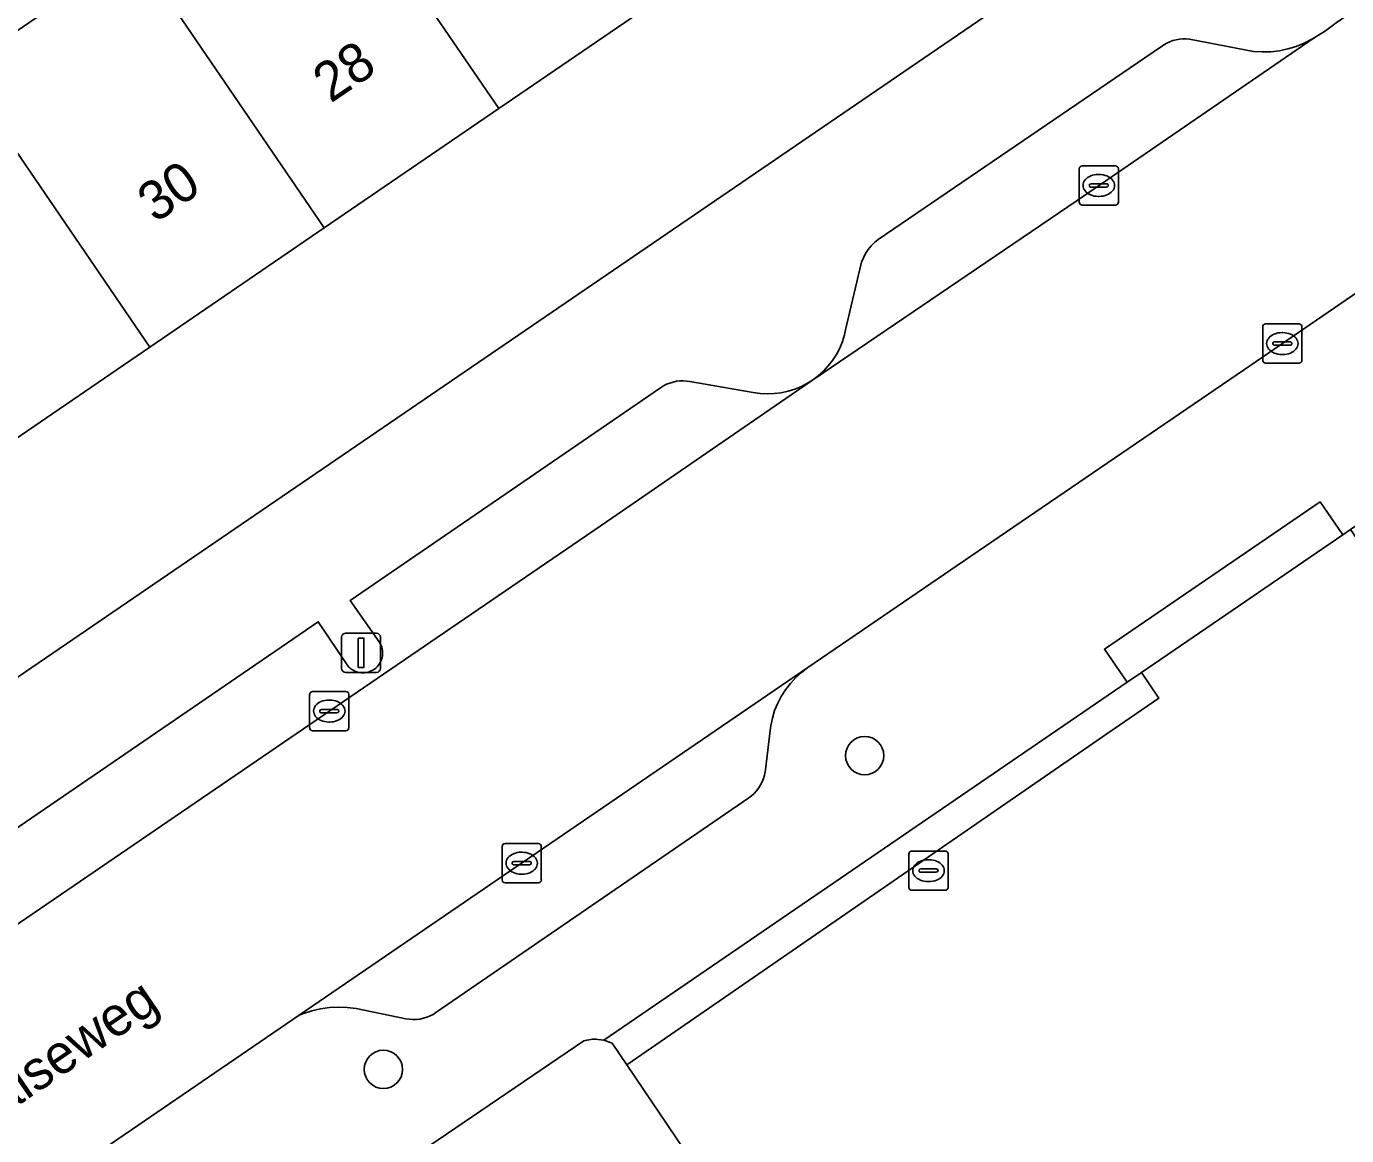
# Model space of a CAD drawing. Extents: x 157445 to 158888, y 383061 to 384688.
# Drawn here: x 158247.86 to 158281.55, y 383719.45 to 383747.74 of the extents above; entities that cross this region are included whole.
import ezdxf

# ---------------------------------------------------------------- set-up
doc = ezdxf.new("R2010")
doc.units = 0
for name, color, linetype in [('IMGEO_Boom', 7, 'Continuous'), ('IMGEO_Erf', 7, 'Continuous'), ('IMGEO_Groenvoorziening', 7, 'Continuous'), ('IMGEO_Kolk', 7, 'Continuous'), ('IMGEO_Lichtmast', 7, 'Continuous'), ('IMGEO_Openbare_ruimte_label', 7, 'Continuous'), ('IMGEO_Pand', 7, 'Continuous'), ('IMGEO_Pand_nummerreeks', 7, 'Continuous'), ('IMGEO_Parkeervlak_open', 7, 'Continuous'), ('IMGEO_Rijbaan_lokaal_open', 7, 'Continuous'), ('IMGEO_Voetpad_gesloten', 7, 'Continuous'), ('IMGEO_Voetpad_open', 7, 'Continuous')]:
    doc.layers.add(name, color=color, linetype=linetype)

msp = doc.modelspace()

# ---------------------------------------------------------------- linework, layer by layer
at = {"layer": 'IMGEO_Boom'}
for centre in [(158269.25, 383729.141), (158256.968, 383721.134)]:
    msp.add_circle(centre, 0.489, dxfattribs=at)
at = {"layer": 'IMGEO_Erf'}
msp.add_lwpolyline([(158275.244, 383750), (158276.273, 383750.703), (158273.392, 383754.863), (158268.814, 383751.734), (158266.277, 383750), (158264.363, 383748.692), (158259.911, 383745.649), (158255.46, 383742.607), (158251.008, 383739.564), (158246.557, 383736.522), (158242.105, 383733.479), (158237.653, 383730.437), (158233.201, 383727.394), (158228.626, 383724.267), (158231.45, 383720.093)], close=True, dxfattribs=at)
at = {"layer": 'IMGEO_Groenvoorziening'}
msp.add_lwpolyline([(158276.313, 383731.261), (158275.946, 383731.01), (158262.596, 383721.878), (158262.806, 383721.806), (158263.183, 383721.249), (158275.456, 383729.709), (158276.755, 383730.605)], close=True, dxfattribs=at)
for points in [[(158262.079, 383721.862), (158245.028, 383710.284), (158233.32, 383702.286)], [(158274.181, 383704.979), (158272.403, 383707.609), (158263.183, 383721.249), (158262.806, 383721.806), (158262.596, 383721.878), (158262.44, 383721.901)]]:
    msp.add_lwpolyline(points, dxfattribs=at)
msp.add_arc((158262.365, 383720.907), 0.997, 85.6714, 106.6604, dxfattribs=at)
at = {"layer": 'IMGEO_Kolk'}
for p, q in [((158274.725, 383743.26), (158274.725, 383744.112)), ((158274.8, 383744.186), (158275.652, 383744.186)), ((158275.726, 383744.112), (158275.726, 383743.26)), ((158274.984, 383743.68), (158274.984, 383743.692)), ((158275.027, 383743.729), (158275.425, 383743.729)), ((158275.213, 383743.966), (158275.238, 383743.966)), ((158275.468, 383743.692), (158275.468, 383743.68)), ((158275.422, 383743.643), (158275.024, 383743.643)), ((158275.236, 383743.406), (158275.211, 383743.406)), ((158275.652, 383743.186), (158274.8, 383743.186)), ((158279.409, 383739.226), (158279.409, 383740.078)), ((158279.484, 383740.152), (158280.336, 383740.152)), ((158280.41, 383740.078), (158280.41, 383739.226)), ((158279.668, 383739.646), (158279.668, 383739.658)), ((158279.711, 383739.695), (158280.109, 383739.695)), ((158279.897, 383739.932), (158279.922, 383739.932)), ((158280.152, 383739.658), (158280.152, 383739.646)), ((158280.106, 383739.609), (158279.708, 383739.609)), ((158279.92, 383739.372), (158279.895, 383739.372)), ((158280.336, 383739.152), (158279.484, 383739.152)), ((158255.086, 383729.85), (158255.086, 383730.702)), ((158255.161, 383730.776), (158256.013, 383730.776)), ((158255.574, 383730.556), (158255.599, 383730.556)), ((158256.087, 383730.702), (158256.087, 383729.85)), ((158255.345, 383730.27), (158255.345, 383730.282)), ((158255.783, 383730.233), (158255.385, 383730.233)), ((158255.388, 383730.319), (158255.786, 383730.319)), ((158255.829, 383730.282), (158255.829, 383730.27)), ((158255.597, 383729.996), (158255.572, 383729.996)), ((158256.013, 383729.776), (158255.161, 383729.776)), ((158259.997, 383725.969), (158259.997, 383726.821)), ((158260.072, 383726.895), (158260.924, 383726.895)), ((158260.998, 383726.821), (158260.998, 383725.969)), ((158260.485, 383726.675), (158260.51, 383726.675)), ((158270.379, 383725.779), (158270.379, 383726.631)), ((158270.454, 383726.705), (158271.306, 383726.705)), ((158270.867, 383726.485), (158270.892, 383726.485)), ((158271.38, 383726.631), (158271.38, 383725.779)), ((158260.256, 383726.389), (158260.256, 383726.401)), ((158260.694, 383726.352), (158260.296, 383726.352)), ((158260.299, 383726.438), (158260.697, 383726.438)), ((158260.74, 383726.401), (158260.74, 383726.389)), ((158270.638, 383726.199), (158270.638, 383726.211)), ((158271.076, 383726.162), (158270.678, 383726.162)), ((158270.681, 383726.248), (158271.079, 383726.248)), ((158271.122, 383726.211), (158271.122, 383726.199)), ((158260.924, 383725.895), (158260.072, 383725.895)), ((158260.508, 383726.115), (158260.483, 383726.115)), ((158270.89, 383725.925), (158270.865, 383725.925)), ((158271.306, 383725.705), (158270.454, 383725.705))]:
    msp.add_line(p, q, dxfattribs=at)
for points in [[(158274.725, 383743.26), (158274.725, 383744.112)], [(158274.8, 383744.186), (158275.652, 383744.186)], [(158275.726, 383744.112), (158275.726, 383743.26)], [(158275.652, 383743.186), (158274.8, 383743.186)], [(158279.409, 383739.226), (158279.409, 383740.078)], [(158279.484, 383740.152), (158280.336, 383740.152)], [(158280.41, 383740.078), (158280.41, 383739.226)], [(158280.336, 383739.152), (158279.484, 383739.152)], [(158255.086, 383729.85), (158255.086, 383730.702)], [(158255.161, 383730.776), (158256.013, 383730.776)], [(158256.087, 383730.702), (158256.087, 383729.85)], [(158256.013, 383729.776), (158255.161, 383729.776)], [(158259.997, 383725.969), (158259.997, 383726.821)], [(158260.072, 383726.895), (158260.924, 383726.895)], [(158260.998, 383726.821), (158260.998, 383725.969)], [(158270.379, 383725.779), (158270.379, 383726.631)], [(158270.454, 383726.705), (158271.306, 383726.705)], [(158271.38, 383726.631), (158271.38, 383725.779)], [(158260.924, 383725.895), (158260.072, 383725.895)], [(158271.306, 383725.705), (158270.454, 383725.705)]]:
    msp.add_lwpolyline(points, dxfattribs=at)
for centre, radius, start, end in [((158274.802, 383744.11), 0.0765, 91.552, 178.448), ((158274.802, 383744.11), 0.0765, 91.552, 178.448), ((158275.65, 383744.11), 0.0765, 1.552, 88.448), ((158275.65, 383744.11), 0.0765, 1.552, 88.448), ((158275.024, 383743.689), 0.0403, 85.8775, 175.7526), ((158275.021, 383743.679), 0.0366, 178.938, 274.7102), ((158275.425, 383743.686), 0.043, 264.8664, 352.4533), ((158275.429, 383743.691), 0.0386, 1.7309, 96.639), ((158274.802, 383743.262), 0.0765, 181.552, 268.448), ((158274.802, 383743.262), 0.0765, 181.552, 268.448), ((158275.65, 383743.262), 0.0765, 271.552, 358.448), ((158275.65, 383743.262), 0.0765, 271.552, 358.448), ((158279.486, 383740.076), 0.0765, 91.552, 178.448), ((158279.486, 383740.076), 0.0765, 91.552, 178.448), ((158280.334, 383740.076), 0.0765, 1.552, 88.448), ((158280.334, 383740.076), 0.0765, 1.552, 88.448), ((158279.708, 383739.655), 0.0403, 85.8775, 175.7526), ((158279.705, 383739.645), 0.0366, 178.938, 274.7102), ((158280.109, 383739.652), 0.043, 264.8664, 352.4533), ((158280.113, 383739.657), 0.0386, 1.7309, 96.639), ((158279.486, 383739.228), 0.0765, 181.552, 268.448), ((158279.486, 383739.228), 0.0765, 181.552, 268.448), ((158280.334, 383739.228), 0.0765, 271.552, 358.448), ((158280.334, 383739.228), 0.0765, 271.552, 358.448), ((158255.163, 383730.7), 0.0765, 91.552, 178.448), ((158255.163, 383730.7), 0.0765, 91.552, 178.448), ((158256.011, 383730.7), 0.0765, 1.552, 88.448), ((158256.011, 383730.7), 0.0765, 1.552, 88.448), ((158255.385, 383730.279), 0.0403, 85.8775, 175.7526), ((158255.382, 383730.269), 0.0366, 178.938, 274.7102), ((158255.786, 383730.276), 0.043, 264.8664, 352.4533), ((158255.79, 383730.281), 0.0386, 1.7309, 96.639), ((158255.163, 383729.852), 0.0765, 181.552, 268.448), ((158255.163, 383729.852), 0.0765, 181.552, 268.448), ((158256.011, 383729.852), 0.0765, 271.552, 358.448), ((158256.011, 383729.852), 0.0765, 271.552, 358.448), ((158260.074, 383726.819), 0.0765, 91.552, 178.448), ((158260.074, 383726.819), 0.0765, 91.552, 178.448), ((158260.922, 383726.819), 0.0765, 1.552, 88.448), ((158260.922, 383726.819), 0.0765, 1.552, 88.448), ((158270.456, 383726.629), 0.0765, 91.552, 178.448), ((158270.456, 383726.629), 0.0765, 91.552, 178.448), ((158271.304, 383726.629), 0.0765, 1.552, 88.448), ((158271.304, 383726.629), 0.0765, 1.552, 88.448), ((158260.296, 383726.398), 0.0403, 85.8775, 175.7526), ((158260.293, 383726.388), 0.0366, 178.938, 274.7102), ((158260.697, 383726.395), 0.043, 264.8664, 352.4533), ((158260.701, 383726.4), 0.0386, 1.7309, 96.639), ((158270.678, 383726.208), 0.0403, 85.8775, 175.7526), ((158270.675, 383726.198), 0.0366, 178.938, 274.7102), ((158271.079, 383726.205), 0.043, 264.8664, 352.4533), ((158271.083, 383726.21), 0.0386, 1.7309, 96.639), ((158260.074, 383725.971), 0.0765, 181.552, 268.448), ((158260.074, 383725.971), 0.0765, 181.552, 268.448), ((158260.922, 383725.971), 0.0765, 271.552, 358.448), ((158260.922, 383725.971), 0.0765, 271.552, 358.448), ((158270.456, 383725.781), 0.0765, 181.552, 268.448), ((158270.456, 383725.781), 0.0765, 181.552, 268.448), ((158271.304, 383725.781), 0.0765, 271.552, 358.448), ((158271.304, 383725.781), 0.0765, 271.552, 358.448)]:
    msp.add_arc(centre, radius, start, end, dxfattribs=at)
for centre, major_axis, ratio, start_param, end_param in [((158275.212, 383743.686), (-0.387, 0.002), 0.722429, 4.712389, 7.853982), ((158275.237, 383743.686), (-0.39, 0.002), 0.717154, 1.570796, 4.712389), ((158279.896, 383739.652), (-0.387, 0.002), 0.722429, 4.712389, 7.853982), ((158279.921, 383739.652), (-0.39, 0.002), 0.717154, 1.570796, 4.712389), ((158255.573, 383730.276), (-0.387, 0.002), 0.722429, 4.712389, 7.853982), ((158255.598, 383730.276), (-0.39, 0.002), 0.717154, 1.570796, 4.712389), ((158260.484, 383726.395), (-0.387, 0.002), 0.722429, 4.712389, 7.853982), ((158260.509, 383726.395), (-0.39, 0.002), 0.717154, 1.570796, 4.712389), ((158270.866, 383726.205), (-0.387, 0.002), 0.722429, 4.712389, 7.853982), ((158270.891, 383726.205), (-0.39, 0.002), 0.717154, 1.570796, 4.712389)]:
    msp.add_ellipse(centre, major_axis=major_axis, ratio=ratio, start_param=start_param, end_param=end_param, dxfattribs=at)
at = {"layer": 'IMGEO_Lichtmast'}
for p, q in [((158256.002, 383732.263), (158256.792, 383732.263)), ((158256.792, 383732.263), (158256.002, 383732.263)), ((158255.902, 383731.363), (158255.902, 383732.163)), ((158255.902, 383732.163), (158255.902, 383731.363)), ((158256.892, 383732.163), (158256.892, 383731.363)), ((158256.892, 383731.363), (158256.892, 383732.163)), ((158256.792, 383731.263), (158256.002, 383731.263)), ((158256.002, 383731.263), (158256.792, 383731.263))]:
    msp.add_line(p, q, dxfattribs=at)
msp.add_lwpolyline([(158256.322, 383732.138), (158256.472, 383732.138), (158256.472, 383731.388), (158256.322, 383731.388), (158256.322, 383732.138)], dxfattribs=at)
for centre, start, end in [((158256.002, 383732.163), 90, 180), ((158256.002, 383732.163), 90, 180), ((158256.792, 383732.163), 0, 90), ((158256.792, 383732.163), 360, 90), ((158256.002, 383731.363), 180, 270), ((158256.002, 383731.363), 180, 270), ((158256.792, 383731.363), 270, 0), ((158256.792, 383731.363), 270, 0)]:
    msp.add_arc(centre, 0.1, start, end, dxfattribs=at)
at = {"layer": 'IMGEO_Pand'}
for points in [[(158259.524, 383755.771), (158255.072, 383752.729), (158256.938, 383750), (158259.911, 383745.649), (158264.363, 383748.692), (158263.469, 383750)], [(158250.62, 383749.688), (158255.46, 383742.607), (158259.911, 383745.649), (158256.938, 383750), (158255.072, 383752.729), (158251.077, 383750)], [(158250.62, 383749.688), (158246.168, 383746.646), (158251.008, 383739.564), (158255.46, 383742.607)], [(158241.716, 383743.605), (158246.557, 383736.522), (158251.008, 383739.564), (158246.168, 383746.646)]]:
    msp.add_lwpolyline(points, close=True, dxfattribs=at)
at = {"layer": 'IMGEO_Parkeervlak_open'}
for points in [[(158301.094, 383734.058), (158304.262, 383729.417), (158318.912, 383739.463), (158311.696, 383750), (158309.812, 383752.752), (158295.206, 383742.73), (158297.657, 383739.109), (158294.925, 383737.259), (158292.253, 383741.181), (158283.359, 383735.114), (158282.098, 383734.254), (158281.649, 383734.911), (158281.45, 383734.775), (158276.313, 383731.261), (158276.755, 383730.605), (158275.456, 383729.709), (158263.183, 383721.249), (158272.403, 383707.609), (158274.095, 383708.785), (158301.564, 383727.539), (158298.373, 383732.165)], [(158267.916, 383738.718), (158274.673, 383743.3), (158280.721, 383747.449), (158280.664, 383747.416), (158280.467, 383747.315), (158280.262, 383747.232), (158280.051, 383747.168), (158279.834, 383747.123), (158279.615, 383747.098), (158279.394, 383747.092), (158279.173, 383747.106), (158277.543, 383747.415), (158277.458, 383747.424), (158277.372, 383747.425), (158277.286, 383747.419), (158277.201, 383747.405), (158277.118, 383747.383), (158277.038, 383747.354), (158276.96, 383747.318), (158276.885, 383747.275), (158276.815, 383747.226), (158276.797, 383747.212), (158269.591, 383742.311), (158269.5, 383742.231), (158269.416, 383742.143), (158269.341, 383742.048), (158269.274, 383741.947), (158269.217, 383741.84), (158269.169, 383741.729), (158269.157, 383741.694), (158268.765, 383740.002), (158268.736, 383739.876), (158268.682, 383739.704), (158268.613, 383739.536), (158268.529, 383739.376), (158268.431, 383739.223), (158268.32, 383739.08), (158268.196, 383738.947), (158268.061, 383738.826)], [(158267.801, 383731.384), (158254.816, 383722.516), (158254.93, 383722.562), (158255.145, 383722.632), (158255.366, 383722.683), (158255.591, 383722.713), (158255.818, 383722.724), (158256.044, 383722.714), (158256.269, 383722.684), (158257.543, 383722.426), (158257.632, 383722.412), (158257.722, 383722.407), (158257.812, 383722.409), (158257.901, 383722.42), (158257.989, 383722.438), (158258.075, 383722.464), (158258.158, 383722.498), (158258.238, 383722.539), (158258.307, 383722.582), (158266.293, 383728.062), (158266.365, 383728.116), (158266.431, 383728.177), (158266.492, 383728.243), (158266.547, 383728.315), (158266.595, 383728.391), (158266.636, 383728.471), (158266.67, 383728.554), (158266.696, 383728.64), (158266.715, 383728.729), (158266.721, 383728.774), (158266.835, 383729.78), (158266.852, 383729.899), (158266.894, 383730.096), (158266.953, 383730.288), (158267.03, 383730.474), (158267.123, 383730.652), (158267.231, 383730.822), (158267.354, 383730.981), (158267.491, 383731.129), (158267.64, 383731.263)]]:
    msp.add_lwpolyline(points, close=True, dxfattribs=at)
msp.add_lwpolyline([(158234.944, 383716.183), (158262.66, 383735.101), (158267.916, 383738.718), (158267.793, 383738.641), (158267.634, 383738.558), (158267.467, 383738.489), (158267.295, 383738.436), (158267.119, 383738.398), (158266.94, 383738.376), (158266.76, 383738.37), (158266.58, 383738.38), (158266.402, 383738.406), (158264.789, 383738.683), (158264.703, 383738.696), (158264.617, 383738.701), (158264.53, 383738.699), (158264.444, 383738.689), (158264.359, 383738.671), (158264.276, 383738.645), (158264.196, 383738.613), (158264.119, 383738.573), (158264.041, 383738.523), (158256.121, 383733.101), (158256.857, 383732.043), (158256.868, 383732.026), (158256.891, 383731.987), (158256.91, 383731.947), (158256.925, 383731.904), (158256.936, 383731.861), (158256.944, 383731.816), (158256.947, 383731.771), (158256.947, 383731.726), (158256.942, 383731.682), (158256.934, 383731.637), (158256.921, 383731.594), (158256.905, 383731.552), (158256.885, 383731.512), (158256.862, 383731.473), (158256.835, 383731.437), (158256.805, 383731.403), (158256.772, 383731.373), (158256.737, 383731.345), (158256.699, 383731.32), (158256.659, 383731.299), (158256.618, 383731.282), (158256.575, 383731.268), (158256.531, 383731.259), (158256.486, 383731.253), (158256.441, 383731.251), (158256.396, 383731.253), (158256.351, 383731.26), (158256.308, 383731.27), (158256.265, 383731.284), (158256.224, 383731.302), (158256.184, 383731.324), (158256.147, 383731.349), (158256.111, 383731.377), (158256.079, 383731.408), (158255.304, 383732.556), (158236.556, 383719.728)], dxfattribs=at)
at = {"layer": 'IMGEO_Rijbaan_lokaal_open'}
for points in [[(158330.351, 383781.361), (158307.283, 383765.552), (158290.185, 383753.958), (158290.116, 383753.905), (158281.286, 383747.838), (158281.012, 383747.631), (158280.721, 383747.449), (158274.673, 383743.3), (158267.916, 383738.718), (158262.66, 383735.101), (158234.944, 383716.183)], [(158248.547, 383718.234), (158254.816, 383722.516), (158267.801, 383731.384), (158272.686, 383734.719), (158278.94, 383738.991), (158282.459, 383741.394), (158290.097, 383746.61), (158295.037, 383750), (158330.85, 383774.628)]]:
    msp.add_lwpolyline(points, dxfattribs=at)
at = {"layer": 'IMGEO_Voetpad_gesloten'}
msp.add_lwpolyline([(158281.45, 383734.775), (158280.874, 383735.617), (158275.37, 383731.852), (158275.946, 383731.01), (158276.313, 383731.261)], close=True, dxfattribs=at)
at = {"layer": 'IMGEO_Voetpad_open'}
for points in [[(158275.244, 383750), (158231.45, 383720.093)], [(158236.556, 383719.728), (158255.304, 383732.556), (158256.079, 383731.408), (158256.111, 383731.377), (158256.147, 383731.349), (158256.184, 383731.324), (158256.224, 383731.302), (158256.265, 383731.284), (158256.308, 383731.27), (158256.351, 383731.26), (158256.396, 383731.253), (158256.441, 383731.251), (158256.486, 383731.253), (158256.531, 383731.259), (158256.575, 383731.268), (158256.618, 383731.282), (158256.659, 383731.299), (158256.699, 383731.32), (158256.737, 383731.345), (158256.772, 383731.373), (158256.805, 383731.403), (158256.835, 383731.437), (158256.862, 383731.473), (158256.885, 383731.512), (158256.905, 383731.552), (158256.921, 383731.594), (158256.934, 383731.637), (158256.942, 383731.682), (158256.947, 383731.726), (158256.947, 383731.771), (158256.944, 383731.816), (158256.936, 383731.861), (158256.925, 383731.904), (158256.91, 383731.947), (158256.891, 383731.987), (158256.868, 383732.026), (158256.857, 383732.043), (158256.121, 383733.101), (158264.041, 383738.523), (158264.119, 383738.573), (158264.196, 383738.613), (158264.276, 383738.645), (158264.359, 383738.671), (158264.444, 383738.689), (158264.53, 383738.699), (158264.617, 383738.701), (158264.703, 383738.696), (158264.789, 383738.683), (158266.402, 383738.406), (158266.58, 383738.38), (158266.76, 383738.37), (158266.94, 383738.376), (158267.119, 383738.398), (158267.295, 383738.436), (158267.467, 383738.489), (158267.634, 383738.558), (158267.793, 383738.641), (158267.916, 383738.718), (158268.061, 383738.826), (158268.196, 383738.947), (158268.32, 383739.08), (158268.431, 383739.223), (158268.529, 383739.376), (158268.613, 383739.536), (158268.682, 383739.704), (158268.736, 383739.876), (158268.765, 383740.002), (158269.157, 383741.694), (158269.169, 383741.729), (158269.217, 383741.84), (158269.274, 383741.947), (158269.341, 383742.048), (158269.416, 383742.143), (158269.5, 383742.231), (158269.591, 383742.311), (158276.797, 383747.212), (158276.815, 383747.226), (158276.885, 383747.275), (158276.96, 383747.318), (158277.038, 383747.354), (158277.118, 383747.383), (158277.201, 383747.405), (158277.286, 383747.419), (158277.372, 383747.425), (158277.458, 383747.424), (158277.543, 383747.415), (158279.173, 383747.106), (158279.394, 383747.092), (158279.615, 383747.098), (158279.834, 383747.123), (158280.051, 383747.168), (158280.262, 383747.232), (158280.467, 383747.315), (158280.664, 383747.416), (158280.721, 383747.449), (158281.012, 383747.631), (158281.286, 383747.838)], [(158262.44, 383721.901), (158262.596, 383721.878), (158275.946, 383731.01), (158275.37, 383731.852), (158280.874, 383735.617), (158281.45, 383734.775), (158281.649, 383734.911), (158291.796, 383741.852)], [(158282.459, 383741.394), (158278.94, 383738.991), (158272.686, 383734.719), (158267.801, 383731.384), (158267.64, 383731.263), (158267.491, 383731.129), (158267.354, 383730.981), (158267.231, 383730.822), (158267.123, 383730.652), (158267.03, 383730.474), (158266.953, 383730.288), (158266.894, 383730.096), (158266.852, 383729.899), (158266.835, 383729.78), (158266.721, 383728.774), (158266.715, 383728.729), (158266.696, 383728.64), (158266.67, 383728.554), (158266.636, 383728.471), (158266.595, 383728.391), (158266.547, 383728.315), (158266.492, 383728.243), (158266.431, 383728.177), (158266.365, 383728.116), (158266.293, 383728.062), (158258.307, 383722.582), (158258.238, 383722.539), (158258.158, 383722.498), (158258.075, 383722.464), (158257.989, 383722.438), (158257.901, 383722.42), (158257.812, 383722.409), (158257.722, 383722.407), (158257.632, 383722.412), (158257.543, 383722.426), (158256.269, 383722.684), (158256.044, 383722.714), (158255.818, 383722.724), (158255.591, 383722.713), (158255.366, 383722.683), (158255.145, 383722.632), (158254.93, 383722.562), (158254.816, 383722.516), (158248.547, 383718.234)], [(158233.32, 383702.286), (158245.028, 383710.284), (158262.079, 383721.862)]]:
    msp.add_lwpolyline(points, dxfattribs=at)
msp.add_arc((158262.365, 383720.907), 0.997, 85.6714, 106.6604, dxfattribs=at)

# ---------------------------------------------------------------- texts
at = {"layer": 'IMGEO_Openbare_ruimte_label'}
msp.add_text('Lievendaalseweg', height=1, rotation=34.3256, dxfattribs=at).set_placement((158242.764, 383716.869))
at = {"layer": 'IMGEO_Pand_nummerreeks'}
for s, p in [('28', (158255.623, 383745.771)), ('30', (158251.146, 383742.711))]:
    msp.add_text(s, height=1, rotation=34.3512, dxfattribs=at).set_placement(p)

doc.saveas('drawing.dxf')
